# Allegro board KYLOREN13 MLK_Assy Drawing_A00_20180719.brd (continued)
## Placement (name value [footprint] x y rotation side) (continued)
C7205  SC22U6D3V3MX-1-DL-GP  [C603H40]  20.83 75.84 90 bottom
C7206  SCD1U16V2KX-3DLGP  [C402H22]  22.48 79.27 90 top
C7208  SC10U6D3V2MX-2-GP  [C402-TO0D2H28]  11.56 83.33 90 bottom
C7210  SC1U10V2KX-1DLGP  [C402H22]  16.13 83.33 90 top
C7211  SC10U6D3V3MX-DL-GP  [C603H36]  18.67 58.18 0 bottom
C7212  SCD22U10V2KX-2-GP  [C402H22]  18.67 84.47 0 top
C7217  SC220P50V2KX-3DLGP  [C402H22]  20.7 87.78 270 top
C7218  SC220P50V2KX-3DLGP  [C402H22]  22.73 87.78 90 top
C7244  SCD1U16V2KX-3DLGP  [C402H22]  19.68 57.8 0 bottom
C7301  SC1U25V3KX-1-DLGP  [C603H36]  19.68 73.04 180 bottom
C7302  SCD1U25V2KX-1-DL-GP  [C402H22]  21.84 72.92 180 top
C7303  SCD1U25V2KX-1-DL-GP  [C402H22]  22.61 72.92 180 top
C7304  SCD1U25V2KX-1-DL-GP  [C402H22]  23.37 72.92 180 top
C7305  SC10U25V5KX-DL-GP  [C805H58]  25.78 73.55 0 bottom
C7306  SC1U25V2KX-2-GP  [C402H22]  24.13 72.92 180 top
C7307  SCD1U25V2KX-1-DL-GP  [C402H22]  24.89 72.92 180 top
C7401  SC1500P50V2KX-2-DL-GP  [C402H22]  25.27 67.96 180 top
C9106  SC10U6D3V3MX-DL-GP  [C603H36]  157.73 56.15 180 bottom
C9108  SCD1U16V2KX-3DLGP  [C402H22]  158.88 56.53 180 bottom
C9109  SC10U6D3V3MX-DL-GP  [C603H36]  160.66 62.63 270 bottom
C9112  SCD1U16V2KX-3DLGP  [C402H22]  163.56 54.12 180 bottom
C9113  SCD1U16V2KX-3DLGP  [C402H22]  164.34 54.12 180 bottom
C9201  SC1U10V2KX-1DLGP  [C402H22]  172.72 52.22 270 top
CPU1  WHISKEY-LAKE-GP  [BGA1528M2446-1H52]  113.55 78.9 270 bottom
D1701  RB520S30-GP  [SOD523AKH26]  122.17 52.09 90 bottom
D2401  BAT54C-12-GP  [SOT-23-9H44]  109.73 17.8 0 bottom
D2402  RB751V-40H-GP  [SOD323AKH38]  21.74 29.84 90 bottom
D2403  RB520S30-GP  [SOD523AKH26]  87.63 25.42 270 bottom
D2501  BAT54C-12-GP  [SOT-23-9H44]  154.23 77.36 180 bottom
D2502  RB751V-40H-GP  [SOD323AKH38]  158.88 51.33 180 bottom
D2503  BAT54A-11-GP  [SOT-23-9H44]  159.27 73.13 180 bottom
D2601  RB551V30-GP  [SOD323AKH38]  172.85 78.89 0 bottom
D2702  BAT54C-12-GP  [SOT-23-9H44]  6.48 6.62 180 bottom
D4001  RB520S30-GP  [SOD523AKH26]  104.14 19.55 180 bottom
D4002  RB520S30-GP  [SOD523AKH26]  159.26 76.47 180 bottom
D4003  RB520S30-GP  [SOD523AKH26]  161.14 80.87 180 bottom
D4301  P6AF24A-R1-00001-GP  [D4724AKH44]  28.96 74.69 0 bottom
D4302  LBAV99LT1G-1-GP  [SOT23-2D4-312H44]  50.42 13.58 180 bottom
D4303  L30ESD24VC3-2-GP  [SOT23-2D4-312H60]  51.99 16.99 180 bottom
D4304  SMF18A-GP  [SOD123AK-2H43]  145.97 13.23 0 bottom
D4305  RB751V-40H-GP  [SOD323AKH38]  24.26 27.22 90 bottom
D5501  BAT54C-12-GP  [SOT-23-9H44]  124.33 102.63 270 bottom
D5502  BAT54C-12-GP  [SOT-23-9H44]  129.67 98.06 270 bottom
D5701  BAW56-9-GP-U  [SOT23-2D4-312H44]  21.34 61.61 90 bottom
D5702  RB751V-40H-GP  [SOD323AKH38]  27.81 52.22 270 bottom
D6101  RB751V-40H-GP  [SOD323AKH38]  181.61 36.85 180 top
D6102  RB751V-40H-GP  [SOD323AKH38]  184.15 36.85 180 top
D6401  BAT54A-11-GP  [SOT-23-9H44]  130.81 12.97 270 bottom
D7301  NSR20F30NXT5G-GP  [D1608AK-1H13]  26.04 73.3 0 top
D9201  RB751V-40H-GP  [SOD323AKH38]  181.61 48.91 180 top
DB1  DM-ACES-CON14-5-GP-01  [DM-87212-1400N-01]  93.73 15 180 top
DB3  ACES-CON6-58-GP  [50696-00601-001]  96.52 1.16 180 bottom
DCIN1  ACES-CON8-13-GP-U2  [50224-0080N-W02-U]  26.15 83.05 0 bottom
EC1706  SC1KP50V2KX-1DLGP  [C402H22]  152.78 88.28 270 top
EC1707  SCD1U16V2KX-3DLGP  [C402H22]  133.01 50.04 90 bottom
EC1712  SCD1U16V2KX-3DLGP  [C402H22]  129.08 50.85 270 bottom
EC1801  SC10P50V2JN-4DLGP  [C402H22]  127.13 58.82 90 top
EC1803  SC4D7P50V2BN-2-GP  [C402H22]  125.86 59.71 270 bottom
EC1804  SCD1U16V2KX-3DLGP  [C402H22]  156.08 50.06 90 bottom
EC1901  SC10P50V2JN-4DLGP  [C402H22]  27.94 24.53 0 top
EC1903  SC33P50V2JN-3DLGP  [C402H22]  24.89 23.64 270 top
EC2201  SCD1U25V2KX-1-DL-GP  [C402H22]  124.05 83.39 270 top
EC2402  SCD1U25V2KX-1-DL-GP  [C402H22]  100.97 13.2 90 top
EC2403  SCD1U25V2KX-1-DL-GP  [C402H22]  81.56 9.42 180 bottom
EC2501  SC4D7P50V2BN-2-GP  [C402H22]  133.15 61.21 90 bottom
EC2502  SC4D7P50V2BN-2-GP  [C402H22]  150.11 57.8 180 bottom
EC2503  SC10P50V2JN-4DLGP  [C402H22]  136.8 58.73 90 bottom
EC2601  SC10P50V2JN-4DLGP  [C402H22]  163.83 78.89 180 bottom
EC2602  SC10P50V2JN-4DLGP  [C402H22]  163.83 80.41 0 bottom
EC2701  SC10P50V2JN-4DLGP  [C402H22]  30.1 24.15 270 top
EC2709  SCD01U50V2KX-1DLGP  [C402H22]  17.65 14.75 180 bottom
EC2710  SCD01U50V2KX-1DLGP  [C402H22]  5.08 9.54 0 top
EC2711  SCD01U50V2KX-1DLGP  [C402H22]  5.84 9.54 0 top
EC2712  SCD1U25V2KX-1-DL-GP  [C402H22]  19.43 26.43 90 top
EC2713  SCD1U25V2KX-1-DL-GP  [C402H22]  18.16 12.59 90 bottom
EC2714  SCD1U25V2KX-1-DL-GP  [C402H22]  19.43 27.2 90 top
EC2901  SC1KP50V2KX-1DLGP  [C402H22]  19.56 4.08 90 top
EC2902  SC1KP50V2KX-1DLGP  [C402H22]  21.34 4.08 90 top
EC2903  SC1KP50V2KX-1DLGP  [C402H22]  21.31 8.93 270 top
EC2904  SC1KP50V2KX-1DLGP  [C402H22]  24 7.51 0 top
EC2905  SC680P50V2KX-2DLGP  [C402H22]  5.71 12.57 180 bottom
EC2906  SC680P50V2KX-2DLGP  [C402H22]  16.76 26.82 90 bottom
EC2907  SC680P50V2KX-2DLGP  [C402H22]  16.64 22.24 0 bottom
EC2908  SC680P50V2KX-2DLGP  [C402H22]  17.02 23.51 90 bottom
EC3501  SCD1U25V2KX-1-DL-GP  [C402H22]  19.18 43.71 90 top
EC4301  SC10U25V3MX-GP  [C603H40]  25.78 76.73 90 bottom
EC4302  SCD1U25V2KX-1-DL-GP  [C402H22]  26.54 75.58 270 top
EC4306  SC10P50V2JN-4DLGP  [C402H22]  30.1 39.13 90 top
EC4307  SC1KP50V2KX-1DLGP  [C402H22]  148.74 14.06 180 bottom
EC4308  SCD1U50V3KX-DL-GP  [C603H35]  147.75 14.29 180 bottom
EC4309  SC10P50V2JN-4DLGP  [C402H22]  164.21 22.8 0 bottom
EC4310  SC10P50V2JN-4DLGP  [C402H22]  163.86 23.94 270 bottom
EC4311  SCD1U25V2KX-1-DL-GP  [C402H22]  27.81 81.04 270 top
EC4312  SC1KP50V2KX-1DLGP  [C402H22]  26.54 76.35 270 top
EC4313  SCD1U25V2KX-1-DL-GP  [C402H22]  26.54 77.11 270 top
EC4534  SC2D2U25V5KX-2-GP  [C805H54]  55.88 21.86 270 bottom
EC4701  SCD1U25V2KX-1-DL-GP  [C402H22]  92.88 72.42 90 top
EC5001  SCD1U25V2KX-1-DL-GP  [C402H22]  119.75 76.48 270 top
EC5501  SC8P50V2DN-1DL-GP  [C402H22]  100.97 101.87 0 top
EC5503  SC33P50V2JN-3DLGP  [C402H22]  114.05 100.17 180 top
EC5504  SC33P50V2JN-3DLGP  [C402H22]  114.43 98.95 90 top
EC5505  SCD1U50V3KX-DL-GP  [C603H35]  50.04 88.66 270 bottom
EC5506  SC33P50V2JN-3DLGP  [C402H22]  59.69 91.97 90 top
EC6501  SC33P50V2JN-3DLGP  [C402H22]  144.65 10.43 270 top
EC6502  SC33P50V2JN-3DLGP  [C402H22]  144.65 9.67 270 top
EC6503  SC33P50V2JN-3DLGP  [C402H22]  132.72 10.79 270 top
EC6504  SC33P50V2JN-3DLGP  [C402H22]  132.72 10.03 270 top
EC8901  SCD1U25V2KX-1-DL-GP  [C402H22]  132.33 106.95 0 bottom
EC8902  SCD1U25V2KX-1-DL-GP  [C402H22]  97.41 99.33 180 top
EC8903  SCD1U25V2KX-1-DL-GP  [C402H22]  93.73 98.93 270 top
EC8904  SCD1U25V2KX-1-DL-GP  [C402H22]  68.71 80.54 270 top
EC8905  SC1U10V2KX-1DLGP  [C402H22]  96.31 86.13 180 top
EC8906  SCD1U25V2KX-1-DL-GP  [C402H22]  99.87 82.58 0 top
EC8907  SCD1U25V2KX-1-DL-GP  [C402H22]  122.1 99.36 180 top
EC8908  SCD1U25V2KX-1-DL-GP  [C402H22]  147.8 20.29 180 top
EC8909  SCD1U25V2KX-1-DL-GP  [C402H22]  157.28 29.96 270 top
EC8910  SCD1U25V2KX-1-DL-GP  [C402H22]  158.12 21.56 270 top
EC8911  SCD1U25V2KX-1-DL-GP  [C402H22]  170.74 53.74 90 top
EC8912  SCD1U25V2KX-1-DL-GP  [C402H22]  47.75 87.67 0 bottom
EC8913  SCD1U25V2KX-1-DL-GP  [C402H22]  52.58 59.89 270 bottom
EC8914  SCD1U25V2KX-1-DL-GP  [C402H22]  125.91 27.3 90 bottom
EC8915  SCD1U25V2KX-1-DL-GP  [C402H22]  158.83 30.96 270 bottom
EC8916  SCD1U25V2KX-1-DL-GP  [C402H22]  170.74 52.9 90 top
EC8917  SCD1U25V2KX-1-DL-GP  [C402H22]  113.21 23.28 0 top
EC8918  SCD1U25V2KX-1-DL-GP  [C402H22]  80.54 19.5 0 top
EC8919  SCD1U25V2KX-1-DL-GP  [C402H22]  113.67 6.44 0 top
EC8920  SCD1U25V2KX-1-DL-GP  [C402H22]  136.58 5.25 180 top
EC8921  SCD1U25V2KX-1-DL-GP  [C402H22]  112.42 22.45 180 top
EC8922  SCD1U25V2KX-1-DL-GP  [C402H22]  166.37 20.08 90 top
EC8923  SCD1U25V2KX-1-DL-GP  [C402H22]  171.58 34.44 90 top
EC8924  SCD1U25V2KX-1-DL-GP  [C402H22]  186.56 46.25 180 top
EC8925  SCD1U25V2KX-1-DL-GP  [C402H22]  131.95 98.8 180 bottom
EC8926  SCD1U25V2KX-1-DL-GP  [C402H22]  154.38 101.14 0 bottom
EC8927  SCD1U25V2KX-1-DL-GP  [C402H22]  166.88 11.24 90 top
EC8928  SCD1U25V2KX-1-DL-GP  [C402H22]  101.35 24.66 270 bottom
EC8929  SCD1U25V2KX-1-DL-GP  [C402H22]  168.91 45.99 270 bottom
EC8930  SCD1U25V2KX-1-DL-GP  [C402H22]  86.36 51.45 180 top
EC8931  SCD1U25V2KX-1-DL-GP  [C402H22]  132.99 33.77 0 top
EC8932  SCD1U25V2KX-1-DL-GP  [C402H22]  142.65 46.09 90 top
EC8933  SCD1U25V2KX-1-DL-GP  [C402H22]  120.34 58.65 90 top
EC8934  SCD1U25V2KX-1-DL-GP  [C402H22]  120.31 60.66 90 top
EC8937  SCD1U25V2KX-1-DL-GP  [C402H22]  71.5 86.38 180 top
EC8938  SCD1U25V2KX-1-DL-GP  [C402H22]  71.5 73.81 0 top
EC8939  SCD1U25V2KX-1-DL-GP  [C402H22]  118.36 32.81 180 top
EC8940  SCD1U25V2KX-1-DL-GP  [C402H22]  55.88 48.66 180 top
EC8941  SCD1U25V2KX-1-DL-GP  [C402H22]  49.15 43.83 270 top
EC8942  SCD1U25V2KX-1-DL-GP  [C402H22]  69.9 32.63 270 top
EC8943  SCD1U25V2KX-1-DL-GP  [C402H22]  50.31 66.31 270 top
EC8944  SCD1U25V2KX-1-DL-GP  [C402H22]  57.36 55.26 90 top
EC8945  SCD1U25V2KX-1-DL-GP  [C402H22]  44.31 49.98 270 top
EC8946  SCD1U25V2KX-1-DL-GP  [C402H22]  42.08 23.06 270 top
EC8947  SCD1U25V2KX-1-DL-GP  [C402H22]  55.32 20 0 top
EC8948  SCD1U25V2KX-1-DL-GP  [C402H22]  73.41 29.72 180 top
EC8949  SCD1U25V2KX-1-DL-GP  [C402H22]  121.16 30.12 90 top
EC8950  SCD1U25V2KX-1-DL-GP  [C402H22]  85.67 24.65 0 top
ED301  AZ5125-02S-R7G-GP  [SOT23-2D4-312H46]  117.73 98.06 180 bottom
ED1701  AZ5125-02S-R7G-GP  [SOT23-2D4-312H46]  137.41 53.49 180 bottom
ED1702  AZ5125-02S-R7G-GP  [SOT23-2D4-312H46]  163.45 83.2 180 bottom
ED1703  AZ5125-02S-R7G-GP  [SOT23-2D4-312H46]  167 83.2 180 bottom
ED1704  AZ5125-02S-R7G-GP  [SOT23-2D4-312H46]  157.73 83.2 180 bottom
ED1801  AZ5125-02S-R7G-GP  [SOT23-2D4-312H46]  135.48 49.86 0 bottom
ED2403  AZ5125-02S-R7G-GP  [SOT23-2D4-312H46]  108.46 15 180 bottom
ED2901  AZ5125-02S-R7G-GP  [SOT23-2D4-312H46]  4.83 15.89 270 bottom
ED2902  AZ5125-02S-R7G-GP  [SOT23-2D4-312H46]  19.56 26.18 90 bottom
ED2903  AZ5125-02S-R7G-GP  [SOT23-2D4-312H46]  16.51 29.74 180 bottom
ED3501  L05ESDL5V0NA-4-GP  [SLP2510P8-1H22]  18.67 40.15 90 top
ED3503  AZC099-04S-2-GP  [SOT-6H58]  19.56 35.96 0 bottom
ED4304  LBAV99LT1G-1-GP  [SOT23-2D4-312H44]  161.34 20.29 0 bottom
ED4305  LBAV99LT1G-1-GP  [SOT23-2D4-312H44]  162.86 25.93 180 bottom
ED4306  LBAV99LT1G-1-GP  [SOT23-2D4-312H44]  161.34 22.78 0 bottom
ED5501  AZC099-04S-2-GP  [SOT-6H58]  121.28 99.21 270 bottom
ED5502  AZ5125-02S-R7G-GP  [SOT23-2D4-312H46]  47.37 90.32 180 bottom
ED5701  AZ1043-04F-R7G-GP  [DFN10G2510H22]  17.14 61.11 90 top
ED5702  AZ1043-04F-R7G-GP  [DFN10G2510H22]  17.14 65.04 270 top
ED5703  AZ1043-04F-R7G-GP  [DFN10G2510H22]  15.62 62.63 90 bottom
ED6301  L05ESDL5V0NA-4-GP  [SLP2510P8-1H22]  169.67 15.26 90 top
ED6401  AZ5125-02S-R7G-GP  [SOT23-2D4-312H46]  111.76 15.13 270 bottom
ED7301  L05ESDL5V0NA-4-GP  [SLP2510P8-1H22]  16 77.79 270 top
ED7302  L05ESDL5V0NA-4-GP  [SLP2510P8-1H22]  15.11 89.55 270 top
ED7303  L05ESDL5V0NA-4-GP  [SLP2510P8-1H22]  14.73 86.25 90 top
ED7304  AZ5315-02F-GP  [SOT883-1D0-321H20]  21.72 90.06 0 top
ED7305  AZ5315-02F-GP  [SOT883-1D0-321H20]  32.51 85.62 0 bottom
ED9202  AZC099-04S-2-GP  [SOT-6H58]  173.02 48.99 270 bottom
EL3505  COIL-90OHM-100MHZ-5-GP  [L125100-4P-4H24]  18.92 38.88 270 bottom
EL4301  0R0805-PAD-2-GP-U  [0R0805-PAD-1-U]  30.71 77.11 90 top
EL4302  0R0805-PAD-2-GP-U  [0R0805-PAD-1-U]  30.71 75.2 90 top
EL4303  0R0805-PAD-2-GP-U  [0R0805-PAD-1-U]  26.04 79.14 180 top
EL4304  0R0805-PAD-2-GP-U  [0R0805-PAD-1-U]  24.13 79.14 180 top
EL5501  COIL-90OHM-100MHZ-5-GP  [L125100-4P-4H24]  124.21 99.84 0 bottom
EL6601  COIL-90OHM-100MHZ-5-GP  [L125100-4P-4H24]  174.04 43.33 90 top
EL6603  COIL-90OHM-100MHZ-5-GP  [L125100-4P-4H24]  175.64 43.33 90 top
EL7201  COIL-90OHM-100MHZ-5-GP  [L125100-4P-4H24]  16.64 85.36 180 top
EL7202  COIL-90OHM-100MHZ-5-GP  [L125100-4P-4H24]  16.64 87.14 180 top
EL7301  0R5J-5-GP  [R805H24]  23.88 73.55 180 bottom
EL7302  0R5J-5-GP  [R805H24]  21.97 73.55 180 bottom
ER2901  0R0402-PAD-2-GP  [0R0402-PAD-1]  23.11 7.51 0 top
ER2902  0R0402-PAD-2-GP  [0R0402-PAD-1]  21.92 7.46 0 top
ER2903  0R0402-PAD-2-GP  [0R0402-PAD-1]  21.23 4.84 90 top
ER2904  0R0402-PAD-2-GP  [0R0402-PAD-1]  19.56 4.84 90 top
F5502  POLYSW-1D1A6V-9-GP-U  [POLYSW-2114H30]  106.63 103.14 0 top
F5503  POLYSW-1D1A24V-GP-U  [POLYSW-4633-UH43]  54.48 91.61 0 bottom
F5504  POLYSW-1D1A6V-9-GP-U  [POLYSW-2114H30]  57.4 92.6 90 top
F5701  POLYSW-1D1A6V-9-GP-U  [POLYSW-2114H30]  15.75 65.68 180 bottom
F6501  POLYSW-1D1A6V-9-GP-U  [POLYSW-2114H30]  71.5 15.89 270 bottom
FAN1  ACES-CON4-29-GP  [50224-0040N-001]  168.55 75.3 180 bottom
FC1102  SC2D2U6D3V2MX-DL-GP  [C402H22]  119.45 55.75 90 top
FC1103  SC2D2U6D3V2MX-DL-GP  [C402H22]  110.74 59.33 270 top
FC1801  SC4D7P50V2BN-2-GP  [C402H22]  125.86 58.95 270 bottom
FC2701  SC10P50V2JN-4DLGP  [C402H22]  30.61 19.32 180 top
FC5501  SC10P50V2JN-4DLGP  [C402H22]  103 103.27 90 top
FC5502  SC10P50V2JN-4DLGP  [C402H22]  104.52 101.75 270 top
FC6101  SC10P50V2JN-4DLGP  [C402H22]  178 35.83 270 top
FC8906  SC4D7P50V2BN-2-GP  [C402H22]  167.26 51.58 180 bottom
FC8907  SC4D7P50V2BN-2-GP  [C402H22]  168.28 55.9 270 bottom
FC8914  SC4D7P50V2BN-2-GP  [C402H22]  46.1 51.07 270 top
FC8916  SC4D7P50V2BN-2-GP  [C402H22]  170.74 52.09 90 top
FC8917  SC4D7P50V2BN-2-GP  [C402H22]  46.1 51.83 270 top
FC8919  SC4D7P50V2BN-2-GP  [C402H22]  56.13 23.26 270 bottom
FC8920  SC4D7P50V2BN-2-GP  [C402H22]  42.93 29.99 180 top
FC8925  SC4D7P50V2BN-2-GP  [C402H22]  172.29 41.17 90 top
FC8930  SC4D7P50V2BN-2-GP  [C402H22]  172.29 42 90 top
FC8933  SC4D7P50V2BN-2-GP  [C402H22]  157.85 69.91 0 bottom
FC8938  SC4D7P50V2BN-2-GP  [C402H22]  78.99 15 270 top
FC8940  SC4D7P50V2BN-2-GP  [C402H22]  171.58 33.67 90 top
FC8941  SC4D7P50V2BN-2-GP  [C402H22]  78.99 15.77 270 top
FC8942  SC4D7P50V2BN-2-GP  [C402H22]  171.58 35.2 90 top
FC8943  SC4D7P50V2BN-2-GP  [C402H22]  145.29 72.15 270 bottom
FC8945  SC4D7P50V2BN-2-GP  [C402H22]  147.7 93.24 90 bottom
FC8946  SC4D7P50V2BN-2-GP  [C402H22]  64.05 49.94 0 bottom
FC8947  SC4D7P50V2BN-2-GP  [C402H22]  65.45 49.94 0 bottom
FC8948  SC4D7P50V2BN-2-GP  [C402H22]  110.91 50.57 0 bottom
FC8949  SC4D7P50V2BN-2-GP  [C402H22]  139.74 48.54 0 bottom
FC8950  SC4D7P50V2BN-2-GP  [C402H22]  99.61 34.32 180 bottom
FC8951  SC4D7P50V2BN-2-GP  [C402H22]  52.45 30.24 180 bottom
FC8952  SC4D7P50V2BN-2-GP  [C402H22]  82.72 30.63 180 bottom
FC8953  SC4D7P50V2BN-2-GP  [C402H22]  101.22 30.37 180 bottom
FC8954  SC4D7P50V2BN-2-GP  [C402H22]  132.21 29.61 180 bottom
FPR1  PTWO-CON8-11-GP  [FH52-8S-D5SH]  178.65 49.2 270 bottom
FSW1  SW-SLIDE3P-11-GP  [MSS3-Q-T-R]  33.02 10.56 0 bottom
G1801  GAP-OPEN  [CON2O-U]  153.67 49.17 90 bottom
G5701  GAP-CLOSE-PWR-3-GP  [GAP-CLOSE-PWR-3]  22.89 32.02 180 bottom
H1  HOLE335R178-GP  [HOLE335R178]  29.05 94.3 180 bottom
H2  HOLE335R178-GP  [HOLE335R178]  10.95 13.15 180 bottom
H3  HOLE335R178-GP  [HOLE335R178]  104.05 4.3 180 bottom
H5  HOLE335R178-GP  [HOLE335R178]  166.55 89.9 180 bottom
H6  HOLE276R150-GP  [HOLE276R150]  142.35 92 180 bottom
H7  HOLE276R150-GP  [HOLE276R150]  81.35 92 180 bottom
H8  HOLE276R150-GP  [HOLE276R150]  142.35 67.7 180 bottom
H9  HOLE276R150-GP  [HOLE276R150]  81.35 67.7 180 bottom
H10  HOLE335R178-GP  [HOLE335R178]  152.05 34.95 180 bottom
HALL1  HGDEDM013A-GP  [OPLGA4-0913H22]  4.3 73 180 top
HDMI1  SKT-HDMI23-167-GP-U  [SKT-HDMI23-188137-4]  4.6 61.5 90 bottom
HPMIC1  AUDIO-JK569-GP  [2SJ3095-099111F]  3.85 24.1 90 bottom
HS1  STF237R113H62-10-GP  [STF237R113H62]  12.05 73.8 180 bottom
IOBD1  STAR-CON50-2-GP-U  [300E50-1030RA-G4]  173.05 40.8 180 bottom
KBBD1  PTWO-CON30-18-GP  [196528-30041-3]  52.05 8.3 180 bottom
KBBL1  ACES-CON4-90-GP-U  [50698-00401-W01-U]  74.05 6.3 180 bottom
L5701  0R0603-PAD-2-GP-U  [0R0603-PAD-1-U]  26.77 54.35 0 bottom
L5702  0R0603-PAD-2-GP-U  [0R0603-PAD-1-U]  26.8 46.88 90 bottom
L5703  0R0603-PAD-2-GP-U  [0R0603-PAD-1-U]  26.8 45.48 90 bottom
L5704  0R0603-PAD-2-GP-U  [0R0603-PAD-1-U]  26.8 48.15 90 bottom
L5705  0R0603-PAD-2-GP-U  [0R0603-PAD-1-U]  26.8 44.21 90 bottom
L7101  0R0402-PAD-2-GP  [0R0402-PAD-1]  33.4 87.52 90 top
LCD1  STAR-CON50-2-GP-U  [300E50-1030RA-G4]  99.25 102.3 0 bottom
LED1  PTWO-CON4-21-GP  [196335-04021-3]  114.55 6.3 180 bottom
NOREF  -  []  91.24 68.69 90 top
NOREF#2  -  []  2.93 74.52 0 top
NOREF#3  -  []  0 -17 0 top
NOREF#4  -  [unnamed#2]  -4.38 11.53 0 top
NOREF#5  -  [unnamed#2]  176.83 102.77 0 top
NOREF#6  -  []  7.62 1.54 0 top
NOREF#7  *  [unnamed#2]  183.11 -103.1 0 top
NOREF#8  -  [unnamed#2]  -5.04 49.85 0 top
NOREF#9  -  []  138.6 92.95 90 top
NOREF#10  -  []  160.69 93.99 90 top
NOREF#11  -  [unnamed#2]  0.41 98.53 0 top
NOREF#12  -  []  138.6 143.04 0 top
NOREF#13  -  []  105.35 67.59 90 top
NOREF#14  -  []  -1.59 85.52 0 top
NOREF#15  -  [unnamed#2]  191.69 -99.25 0 top
NOREF#16  -  []  -1.59 85.52 0 top
NOREF#17  *  [unnamed#2]  154.56 92.47 0 top
NOREF#18  -  []  12.13 74.44 90 top
NOREF#19  -  [unnamed#2]  196.16 -13.78 0 top
NOREF#20  -  []  -2.03 -54.85 270 top
NOREF#21  *  [unnamed#2]  32.38 23.51 0 top
NOREF#22  -  []  90.55 66.9 0 top
NOREF#23  -  []  12.13 74.44 90 top
NOREF#24  -  []  160.69 93.49 90 top
NOREF#25  -  []  139.14 137.04 0 top
NOREF#26  -  []  0 -17 0 top
NOREF#27  *  [unnamed#2]  160.78 4.21 0 top
NOREF#28  -  []  94.5 65.9 0 top
NOREF#29  -  []  201.4 92.45 0 top
NOREF#30  -  [unnamed#2]  197.54 -51.26 0 top
NOREF#31  -  []  91.24 68.04 0 top
NOREF#32  *  [unnamed#2]  183.91 103.69 0 top
NOREF#33  -  []  144.59 142.49 0 top
NOREF#34  -  []  -1.59 85.52 0 top
NOREF#35  -  [unnamed#2]  63.02 105.18 0 top
NOREF#36  *  [unnamed#2]  24 89.68 0 top
NOREF#37  *  [unnamed#2]  4.14 104.66 0 top
NOREF#38  -  [unnamed#2]  3.7 3.3 0 top
NOREF#39  -  []  0 -17 0 top
NOREF#40  -  [unnamed#2]  156.85 107.4 0 top
NOREF#41  -  []  2.93 74.52 0 top
NOREF#42  -  []  127.15 6.19 0 top
NOREF#43  -  []  96.27 51.45 0 top
NOREF#44  -  []  17.96 109.21 180 top
NOREF#45  -  []  139.14 98.94 90 top
NOREF#46  *  [unnamed#2]  18.75 9.95 0 top
NOREF#47  -  [unnamed#2]  189.87 31.26 0 top
NOREF#48  -  []  68.45 17.16 0 top
NOREF#49  -  [unnamed#2]  128.75 -106.86 0 top
NOREF#50  -  []  12.13 74.44 90 top
NOREF#51  -  [unnamed#2]  16.4 -103.41 0 top
NOREF#52  -  []  173.81 -111.28 0 top
NOREF#53  -  []  0 -17 0 top
NOREF#54  -  [unnamed#2]  -5.37 58.98 0 top
NOREF#55  -  []  2.93 74.52 0 top
NOREF#56  -  [unnamed#2]  197.83 -61.34 0 top
NOREF#57  -  []  65.45 -8.19 180 top
NOREF#58  *  [unnamed#2]  183.11 -103.1 180 bottom
NOREF#59  *  [unnamed#2]  161.09 31.23 180 bottom
NOREF#60  -  []  7.62 1.54 180 bottom
NOREF#61  *  [unnamed#2]  183.91 103.69 180 bottom
NOREF#62  -  []  7.75 97.68 180 bottom
NOREF#63  -  []  -2.03 -69.58 90 bottom
NOREF#64  -  []  100.58 50.18 180 bottom
NOREF#65  *  [unnamed#2]  4.14 104.66 180 bottom
NOREF#66  -  []  149.86 88.41 180 bottom
NOREF#67  *  [unnamed#2]  154.56 92.47 180 bottom
NOREF#68  -  []  180.21 33.17 180 bottom
NOREF#69  -  []  84.2 75.46 180 bottom
NOREF#70  *  [unnamed#2]  89.79 57.93 180 bottom
NOREF#71  -  []  196.98 -94.72 180 bottom
NOREF#72  *  [unnamed#2]  12.32 6.75 180 bottom
NOREF#73  *  [unnamed#2]  36.7 96.54 180 bottom
PC1001  SC22U6D3V3MX-1-DL-GP  [C603H40]  72.39 69.23 0 bottom
PC1002  SC22U6D3V3MX-1-DL-GP  [C603H40]  68.58 79.27 270 top
PC1003  SC22U6D3V3MX-1-DL-GP  [C603H40]  89.58 87.66 0 top
PC1004  SC22U6D3V3MX-1-DL-GP  [C603H40]  110.48 81.86 90 top
PC1005  SC22U6D3V3MX-1-DL-GP  [C603H40]  105.45 77.37 270 top
PC1006  SC22U6D3V3MX-1-DL-GP  [C603H40]  68.45 86.63 0 bottom
PC1007  SC22U6D3V3MX-1-DL-GP  [C603H40]  113.94 81.81 270 top
PC1008  SC22U6D3V3MX-1-DL-GP  [C603H40]  113.94 78 270 top
PC1009  SC22U6D3V3MX-1-DL-GP  [C603H40]  69.72 86.63 0 bottom
PC1010  SC22U6D3V3MX-1-DL-GP  [C603H40]  117.26 79.86 90 top
PC1011  SC22U6D3V3MX-1-DL-GP  [C603H40]  115.28 74.22 0 top
PC1012  SC22U6D3V3MX-1-DL-GP  [C603H40]  116.55 74.22 0 top
PC1013  SC22U6D3V3MX-1-DL-GP  [C603H40]  117.82 74.22 0 top
PC1014  SC22U6D3V3MX-1-DL-GP  [C603H40]  114.01 74.22 0 top
PC1015  SC22U6D3V3MX-1-DL-GP  [C603H40]  113.94 83.08 270 top
PC1016  SC22U6D3V3MX-1-DL-GP  [C603H40]  105.45 76.1 270 top
PC1017  SC22U6D3V3MX-1-DL-GP  [C603H40]  112.18 74.19 0 top
PC1018  SC22U6D3V3MX-1-DL-GP  [C603H40]  68.58 77.62 270 top
PC1019  SC22U6D3V3MX-1-DL-GP  [C603H40]  70.23 73.42 0 top
PC1020  SC22U6D3V3MX-1-DL-GP  [C603H40]  117.26 82.4 90 top
PC1021  SC22U6D3V3MX-1-DL-GP  [C603H40]  110.48 83.13 90 top
PC1022  SC22U6D3V3MX-1-DL-GP  [C603H40]  68.58 75.96 270 top
PC1023  SC22U6D3V3MX-1-DL-GP  [C603H40]  68.58 85.24 270 top
PC1024  SC22U6D3V3MX-1-DL-GP  [C603H40]  113.94 79.27 270 top
PC1025  SC22U6D3V3MX-1-DL-GP  [C603H40]  113.94 80.54 270 top
PC1026  SC22U6D3V3MX-1-DL-GP  [C603H40]  68.58 81.93 270 top
PC1027  SC22U6D3V3MX-1-DL-GP  [C603H40]  91.36 87.78 0 top
PC1028  SC22U6D3V3MX-1-DL-GP  [C603H40]  110.48 80.59 90 top
PC1029  SC22U6D3V3MX-1-DL-GP  [C603H40]  88.27 87.65 0 top
PC1030  SC22U6D3V3MX-1-DL-GP  [C603H40]  116.84 88.16 0 top
PC1031  SC22U6D3V3MX-1-DL-GP  [C603H40]  110.49 76.85 90 top
PC1032  SC22U6D3V3MX-1-DL-GP  [C603H40]  110.48 79.32 90 top
PC1034  SC22U6D3V3MX-1-DL-GP  [C603H40]  68.58 83.58 270 top
PC1036  SC22U6D3V3MX-1-DL-GP  [C603H40]  68.58 77.62 90 bottom
PC1037  SC22U6D3V3MX-1-DL-GP  [C603H40]  73.02 56.74 270 bottom
PC1038  SC22U6D3V3MX-1-DL-GP  [C603H40]  101.52 84.99 90 top
PC1039  SC22U6D3V3MX-1-DL-GP  [C603H40]  77.98 63.14 270 bottom
PC1040  SC22U6D3V3MX-1-DL-GP  [C603H40]  92.37 71.4 90 top
PC1041  SC22U6D3V3MX-1-DL-GP  [C603H40]  97.71 83.08 90 top
PC1042  SC22U6D3V3MX-1-DL-GP  [C603H40]  101.27 75.46 270 top
PC1043  SC22U6D3V3MX-1-DL-GP  [C603H40]  88.31 85.12 180 top
PC1044  SC22U6D3V3MX-1-DL-GP  [C603H40]  101.27 76.73 270 top
PC1045  SC22U6D3V3MX-1-DL-GP  [C603H40]  67.82 66.69 90 bottom
PC1046  SC22U6D3V3MX-1-DL-GP  [C603H40]  101.26 78 270 top
PC1047  SC22U6D3V3MX-1-DL-GP  [C603H40]  85.03 78.66 0 top
PC1048  SC22U6D3V3MX-1-DL-GP  [C603H40]  97.71 81.81 90 top
PC1049  SC22U6D3V3MX-1-DL-GP  [C603H40]  92.63 86.13 180 top
PC1050  SC22U6D3V3MX-1-DL-GP  [C603H40]  97.71 75.46 90 top
PC1051  SC22U6D3V3MX-1-DL-GP  [C603H40]  77.98 60.6 270 bottom
PC1052  SC22U6D3V3MX-1-DL-GP  [C603H40]  90.85 85.12 180 top
PC1053  SC22U6D3V3MX-1-DL-GP  [C603H40]  87.04 85.12 180 top
PC1054  SC22U6D3V3MX-1-DL-GP  [C603H40]  97.41 85.74 180 top
PC1055  SC22U6D3V3MX-1-DL-GP  [C603H40]  85.77 85.12 180 top
PC1056  SC22U6D3V3MX-1-DL-GP  [C603H40]  90.59 75.97 180 top
PC1057  SC22U6D3V3MX-1-DL-GP  [C603H40]  74.3 70.63 90 bottom
PC1058  SC22U6D3V3MX-1-DL-GP  [C603H40]  97.71 76.73 90 top
PC1059  SC22U6D3V3MX-1-DL-GP  [C603H40]  89.58 85.12 180 top
PC1060  SC22U6D3V3MX-1-DL-GP  [C603H40]  93.39 73.43 90 top
PC1061  SC22U6D3V3MX-1-DL-GP  [C603H40]  97.71 78 90 top
PC1062  SC22U6D3V3MX-1-DL-GP  [C603H40]  97.71 79.27 90 top
PC1063  SC22U6D3V3MX-1-DL-GP  [C603H40]  86.3 78.66 0 top
PC1064  SC22U6D3V3MX-1-DL-GP  [C603H40]  67.82 68.09 90 bottom
PC1065  SC22U6D3V3MX-1-DL-GP  [C603H40]  68.07 56.91 90 bottom
PC1066  SC22U6D3V3MX-1-DL-GP  [C603H40]  97.71 80.54 90 top
PC1067  SC22U6D3V3MX-1-DL-GP  [C603H40]  101.26 79.27 270 top
PC1068  SC22U6D3V3MX-1-DL-GP  [C603H40]  77.98 61.87 270 bottom
PC1069  SC22U6D3V3MX-1-DL-GP  [C603H40]  73.02 58.01 270 bottom
PC1070  SC22U6D3V3MX-1-DL-GP  [C603H40]  67.82 65.42 90 bottom
PC1071  SC22U6D3V3MX-1-DL-GP  [C603H40]  120.14 77.5 270 top
PC1072  SC22U6D3V3MX-1-DL-GP  [C603H40]  125.01 85.37 90 top
PC1073  SC22U6D3V3MX-1-DL-GP  [C603H40]  119.04 84.23 270 top
PC1074  SC22U6D3V3MX-1-DL-GP  [C603H40]  130.05 107.08 0 bottom
PC1075  SC22U6D3V3MX-1-DL-GP  [C603H40]  120.14 78.77 270 top
PC1076  SC22U6D3V3MX-1-DL-GP  [C603H40]  121.07 82.7 90 top
PC1077  SC22U6D3V3MX-1-DL-GP  [C603H40]  121.07 81.43 90 top
PC1078  SC22U6D3V3MX-1-DL-GP  [C603H40]  131.32 107.08 0 bottom
PC1079  SC22U6D3V3MX-1-DL-GP  [C603H40]  116.64 84.96 90 top
PC1080  SC22U6D3V3MX-1-DL-GP  [C603H40]  110.48 78.05 90 top
PC1081  SC22U6D3V3MX-1-DL-GP  [C603H40]  113.94 76.73 270 top
PC1082  SC22U6D3V3MX-1-DL-GP  [C603H40]  117.26 78.59 90 top
PC1083  SC22U6D3V3MX-1-DL-GP  [C603H40]  117.26 81.13 90 top
PC1084  SC22U6D3V3MX-1-DL-GP  [C603H40]  117.26 77.32 90 top
PC4401  SC10U25V5KX-DL-GP  [C805H58]  36.96 68.98 0 bottom
PC4402  SC10U25V5KX-DL-GP  [C805H58]  33.66 64.2 90 bottom
PC4403  SC10U25V5KX-DL-GP  [C805H58]  36.2 59.84 180 bottom
PC4404  SC10U25V5KX-DL-GP  [C805H58]  33.66 60.52 90 bottom
PC4405  SC10U25V5KX-DL-GP  [C805H58]  33.66 62.35 90 bottom
PC4406  SCD1U25V2KX-1-DL-GP  [C402H22]  50.8 60.98 270 top
PC4407  SC10U25V5KX-DL-GP  [C805H58]  45.09 52.09 90 bottom
PC4408  SC10U25V5KX-DL-GP  [C805H58]  45.09 50.18 90 bottom
PC4409  SC10U25V5KX-DL-GP  [C805H58]  52.6 27.32 0 bottom
PC4410  SC10U25V5KX-DL-GP  [C805H58]  54.48 51.71 180 bottom
PC4411  SC10U25V5KX-DL-GP  [C805H58]  45.09 48.28 90 bottom
PC4412  SC10U25V5KX-DL-GP  [C805H58]  56.26 27.32 0 bottom
PC4413  SC10U25V5KX-DL-GP  [C805H58]  139.06 14.24 180 bottom
PC4414  SC10U25V5KX-DL-GP  [C805H58]  137.16 14.24 180 bottom
PC4415  SC4D7U6D3V3KX-DLGP  [C603H36]  34.04 52.09 90 bottom
PC4416  SC1U25V3KX-1-DLGP  [C603H36]  32.28 50.64 270 bottom
PC4417  SC1U25V3KX-1-DLGP  [C603H36]  34.7 50.64 90 bottom
PC4418  SC22U25V5MX-GP  [C805H58]  54.41 27.32 0 bottom
PC4419  SC1U25V3KX-1-DLGP  [C603H36]  30.73 49.29 90 bottom
PC4420  SCD022U16V2KX-3DLGP  [C402H22]  29.97 48.28 270 top
PC4421  SC4D7U6D3V3KX-DLGP  [C603H36]  40.77 49.42 270 bottom
PC4422  SC4D7U6D3V3KX-DLGP  [C603H36]  33.27 46.37 180 bottom
PC4423  SCD22U25V3KX-DL-GP  [C603H36]  40.01 46.25 90 bottom
PC4424  SC1U25V3KX-1-DLGP  [C603H36]  37.97 41.29 0 bottom
PC4425  SC1U10V2KX-1DLGP  [C402H22]  37.59 42.94 90 bottom
PC4426  SC1U25V3KX-1-DLGP  [C603H36]  36.8 41.29 0 bottom
PC4427  SC10U25V5KX-DL-GP  [C805H58]  143.89 13.1 180 bottom
PC4428  SC10U25V5KX-DL-GP  [C805H58]  141.99 13.1 180 bottom
PC4429  SC4700P25V2KX-4-GP  [C402H22]  36.45 44.47 0 bottom
PC4430  SC10P50V2JN-4DLGP  [C402H22]  30.1 40.66 270 top
PC4431  SCD01U25V2KX-3DLGP  [C402H22]  32.38 40.02 90 top
PC4432  SC1KP50V2KX-1DLGP  [C402H22]  34.04 40.02 90 top
PC4433  SC1KP50V2KX-1DLGP  [C402H22]  32.89 41.29 0 top
PC4434  SC22U25V5MX-GP  [C805H58]  45.09 46.5 90 bottom
PC4435  SC1KP50V2KX-1DLGP  [C402H22]  38.99 56.15 0 top
PC4436  SCD22U25V3KX-DL-GP  [C603H36]  36.58 51.07 180 bottom
PC4437  SC22U25V5MX-GP  [C805H58]  52.7 51.71 180 bottom
PC4438  SCD1U16V2KX-3DLGP  [C402H22]  30.23 38.88 90 bottom
PC4439  SC1U25V3KX-1-DLGP  [C603H36]  39.37 44.47 180 bottom
PC4440  SC1U25V3KX-1-DLGP  [C603H36]  33.66 44.47 90 bottom
PC4445  SCD1U16V2KX-3DLGP  [C402H22]  31.5 29.61 90 bottom
PC4501  SCD1U25V2KX-1-DL-GP  [C402H22]  125.86 24.02 90 bottom
PC4502  SC10U25V5KX-DL-GP  [C805H58]  131.19 25.29 270 bottom
PC4503  SC10U25V5KX-DL-GP  [C805H58]  125.98 25.29 90 bottom
PC4504  SC10U25V5KX-DL-GP  [C805H58]  130.56 23.39 270 bottom
PC4505  SC10U25V5KX-DL-GP  [C805H58]  61.85 15.26 180 bottom
PC4506  SCD1U25V2KX-1-DL-GP  [C402H22]  121.28 25.55 90 bottom
PC4507  SC4D7U6D3V3KX-DLGP  [C603H36]  123.32 17.42 90 bottom
PC4508  SCD1U25V2KX-1-DL-GP  [C402H22]  130.18 18.69 270 bottom
PC4509  SC22U6D3V3MX-1-DL-GP  [C603H40]  115.19 25.8 0 bottom
PC4510  SC22U6D3V3MX-1-DL-GP  [C603H40]  113.79 19.58 180 bottom
PC4511  SC22U6D3V3MX-1-DL-GP  [C603H40]  115.06 19.58 180 bottom
PC4512  SC22U6D3V3MX-1-DL-GP  [C603H40]  117.86 26.43 0 bottom
PC4513  SCD1U25V2KX-1-DL-GP  [C402H22]  112.78 25.67 0 bottom
PC4514  SC22U6D3V3MX-1-DL-GP  [C603H40]  75.18 19.07 180 bottom
PC4515  SC22U6D3V3MX-1-DL-GP  [C603H40]  77.72 19.07 180 bottom
PC4516  SC22U6D3V3MX-1-DL-GP  [C603H40]  76.45 19.07 180 bottom
PC4517  SC22U6D3V3MX-1-DL-GP  [C603H40]  75.69 25.93 0 bottom
PC4518  SCD1U16V2KX-3DLGP  [C402H22]  73.41 25.8 0 bottom
PC4519  SC10U25V5KX-DL-GP  [C805H58]  60.07 15 180 bottom
PC4520  SC4D7U6D3V3KX-DLGP  [C603H36]  64.26 25.67 0 bottom
PC4521  SCD1U25V2KX-1-DL-GP  [C402H22]  68.58 16.78 270 bottom
PC4522  SCD1U25V2KX-1-DL-GP  [C402H22]  60.45 19.58 0 bottom
PC4523  SC10U25V5KX-DL-GP  [C805H58]  59.05 19.58 0 bottom
PC4524  SC2D2U10V3KX-1DLGP-U  [C603H36]  65.53 25.67 0 bottom
PC4525  SC22U6D3V3MX-1-DL-GP  [C603H40]  116.59 26.43 0 bottom
PC4526  SC1KP50V2KX-1DLGP  [C402H22]  62.1 25.93 0 bottom
PC4527  SC22U6D3V3MX-1-DL-GP  [C603H40]  74.42 25.93 0 bottom
PC4528  SCD1U25V2KX-1-DL-GP  [C402H22]  77.98 25.8 0 bottom
PC4529  SC22U6D3V3MX-1-DL-GP  [C603H40]  76.96 25.93 0 bottom
PC4530  SCD1U25V2KX-1-DL-GP  [C402H22]  59.05 23.13 90 bottom
PC4531  SCD1U25V2KX-1-DL-GP  [C402H22]  60.58 25.93 0 bottom
PC4532  SCD1U25V2KX-1-DL-GP  [C402H22]  124.84 20.21 180 top
PC4533  SC1KP50V2KX-1DLGP  [C402H22]  128.52 17.42 90 bottom
PC4542  SC22U6D3V3MX-1-DL-GP  [C603H40]  113.79 25.8 0 bottom
PC4543  SCD1U25V2KX-1-DL-GP  [C402H22]  118.87 26.43 0 bottom
PC4601  SC2200P50V2KX-2DLGP  [C402H22]  39.37 70.76 0 bottom
PC4602  SCD1U25V2KX-1-DL-GP  [C402H22]  47.12 83.97 180 bottom
PC4603  SCD1U25V2KX-1-DL-GP  [C402H22]  37.97 80.03 270 bottom
PC4604  SC330P50V2KX-3-DL-GP  [C402H22]  49.78 83.84 180 bottom
PC4605  SCD047U25V2KX-4-GP  [C402H22]  40.01 78.12 180 bottom
PC4606  SCD22U25V3KX-DL-GP  [C603H36]  41.66 80.41 90 bottom
PC4607  SC1U10V2KX-1DLGP  [C402H22]  44.7 78.38 270 top
PC4608  SCD022U16V2KX-3DLGP  [C402H22]  37.97 78.5 90 bottom
PC4610  SC33P50V2JN-3DLGP  [C402H22]  49.78 81.04 270 top
PC4611  SC2200P50V2KX-2DLGP  [C402H22]  40.01 80.16 180 bottom
PC4612  SC2200P50V2KX-2DLGP  [C402H22]  49.53 82.95 0 top
PC4613  SCD01U25V2KX-3DLGP  [C402H22]  41.91 76.73 90 top
PC4614  SC470P50V2KX-3DLGP  [C402H22]  50.77 76.68 270 top
PC4615  SCD01U50V2KX-1DLGP  [C402H22]  51.18 72.59 270 top
PC4616  SC1KP50V2KX-1DLGP  [C402H22]  40.01 76.47 180 bottom
PC4617  SC1KP50V2KX-1DLGP  [C402H22]  38.35 74.95 0 bottom
PC4618  SC470P50V2KX-3DLGP  [C402H22]  51.31 74.11 270 top
PC4619  SC1KP50V2KX-1DLGP  [C402H22]  50.04 72.54 0 top
PC4620  SCD01U50V2KX-1DLGP  [C402H22]  37.85 72.15 180 bottom
PC4621  SC680P50V2KX-2DLGP  [C402H22]  38.99 72.79 270 bottom
PC4622  SCD01U25V2KX-3DLGP  [C402H22]  48.9 70.38 0 top
PC4623  SC2200P50V2KX-2DLGP  [C402H22]  48.51 84.47 180 top
PC4624  SC33P50V2JN-3DLGP  [C402H22]  39.75 72.03 90 bottom
PC4625  SCD022U16V2KX-3DLGP  [C402H22]  52.83 84.98 270 top
PC4626  SCD022U16V2KX-3DLGP  [C402H22]  51.44 84.35 180 top
PC4628  SCD022U16V2KX-3DLGP  [C402H22]  52.7 75.84 90 top
PC4629  SC330P50V2KX-3-DL-GP  [C402H22]  42.29 75.08 270 top
PC4630  SCD047U25V2KX-4-GP  [C402H22]  50.67 77.87 180 top
PC4631  SCD1U25V2KX-1-DL-GP  [C402H22]  39.75 70.12 90 top
PC4632  SC2200P50V2KX-2DLGP  [C402H22]  40.13 72.28 0 top
PC4633  SCD1U25V2KX-1-DL-GP  [C402H22]  51.94 79.14 270 top
PC4634  SCD047U25V2KX-4-GP  [C402H22]  42.29 68.6 90 top
PC4635  SCD01U25V2KX-3DLGP  [C402H22]  43.43 70.63 180 top
PC4637  SCD01U25V2KX-3DLGP  [C402H22]  42.16 70.76 270 bottom
PC4638  SC330P50V2KX-3-DL-GP  [C402H22]  46.61 70.25 180 bottom
PC4639  SC33P50V2JN-3DLGP  [C402H22]  45.09 70.63 90 top
PC4640  SC2200P50V2KX-2DLGP  [C402H22]  45.47 69.36 180 top
PC4641  SC330P50V2KX-3-DL-GP  [C402H22]  45.85 67.46 180 bottom
PC4642  SC1KP50V2KX-1DLGP  [C402H22]  42.16 69.23 270 bottom
PC4643  SC1KP50V2KX-1DLGP  [C402H22]  44.58 67.84 90 bottom
PC4644  SCD01U50V2KX-1DLGP  [C402H22]  43.31 67.46 180 bottom
PC4651  SC1KP50V2KX-1DLGP  [C402H22]  47.88 82.95 0 top
PC4652  SCD022U16V2KX-3DLGP  [C402H22]  42.67 70.63 180 top
PC4653  SCD047U25V2KX-4-GP  [C402H22]  52.7 77.36 90 top
PC4654  SCD01U25V2KX-3DLGP  [C402H22]  52.7 76.6 90 top
PC4702  SC10U25V3MX-GP  [C603H40]  55.24 67.96 0 bottom
PC4703  SC10U25V3MX-GP  [C603H40]  57.78 67.96 0 bottom
PC4704  SC10U25V3MX-GP  [C603H40]  56.52 67.96 0 bottom
PC4706  SC1KP50V2KX-1DLGP  [C402H22]  62.61 63.77 180 top
PC4707  SCD22U25V3KX-DL-GP  [C603H36]  54.23 62.27 270 bottom
PC4708  SC1U10V2KX-1DLGP  [C402H22]  54.23 59.58 180 bottom
PC4766  SC1U10V2KX-1DLGP  [C402H22]  59.56 59.58 90 top
PC4802  SC10U25V3MX-GP  [C603H40]  59.56 87.65 270 bottom
PC4803  SC10U25V3MX-GP  [C603H40]  59.56 85.87 270 bottom
PC4804  SC10U25V3MX-GP  [C603H40]  57.66 88.16 0 bottom
PC4805  SC10U25V3MX-GP  [C603H40]  56.39 87.39 0 bottom
PC4808  SCD22U25V3KX-DL-GP  [C603H36]  53.72 86.51 270 bottom
PC4809  SC1U10V2KX-1DLGP  [C402H22]  53.98 83.46 90 bottom
PC4810  SC1KP50V2KX-1DLGP  [C402H22]  62.61 84.35 180 top
PC4811  SCD22U25V3KX-DL-GP  [C603H36]  54.99 73.17 270 bottom
PC4812  SC1U10V2KX-1DLGP  [C402H22]  56.26 70.12 90 top
PC4813  SC1KP50V2KX-1DLGP  [C402H22]  63.5 75.2 180 top
PC4814  SC10U25V3MX-GP  [C603H40]  49.15 72.03 90 bottom
PC4815  SC10U25V3MX-GP  [C603H40]  59.44 76.73 270 bottom
PC4816  SC10U25V3MX-GP  [C603H40]  49.15 73.68 90 bottom
PC4817  SC10U25V3MX-GP  [C603H40]  60.07 78 270 bottom
PC4866  SC1U10V2KX-1DLGP  [C402H22]  59.82 69.23 90 top
PC4877  SC1U10V2KX-1DLGP  [C402H22]  51.74 84.73 90 bottom
PC5001  SC2D2U10V3KX-1DLGP-U  [C603H36]  148.84 103.14 0 bottom
PC5002  SC10U25V5KX-DL-GP  [C805H58]  146.43 107.08 0 bottom
PC5003  SC10U25V5KX-DL-GP  [C805H58]  147.07 104.16 180 bottom
PC5004  SCD1U25V2KX-1-DL-GP  [C402H22]  145.67 104.67 180 bottom
PC5005  SCD22U25V3KX-DL-GP  [C603H36]  150.88 105.81 180 bottom
PC5104  SC22U6D3V3MX-1-DL-GP  [C603H40]  142.37 23.77 90 bottom
PC5105  SC22U6D3V3MX-1-DL-GP  [C603H40]  142.37 26.31 90 bottom
PC5107  SC22U6D3V3MX-1-DL-GP  [C603H40]  142.37 27.58 90 bottom
PC5109  SC22U6D3V3MX-1-DL-GP  [C603H40]  142.37 25.04 90 bottom
PC5110  SC1U10V2KX-1DLGP  [C402H22]  151.51 21.48 90 bottom
PC5111  SC10U25V5KX-DL-GP  [C805H58]  155.02 28.72 0 bottom
PC5112  SC2D2U10V3KX-1DLGP-U  [C603H36]  149.48 21.74 90 bottom
PC5113  SC470P50V2KX-3DLGP  [C402H22]  154.56 21.1 0 bottom
PC5114  SCD1U25V2KX-1-DL-GP  [C402H22]  153.03 26.05 270 top
PC5115  SC10U25V5KX-DL-GP  [C805H58]  153.16 28.72 0 bottom
PC5116  SCD1U25V2KX-1-DL-GP  [C402H22]  156.34 28.85 0 bottom
PC5118  SCD1U25V2KX-1-DL-GP  [C402H22]  44.2 23.39 270 bottom
PC5119  SCD1U16V2KX-3DLGP  [C402H22]  49.63 25.01 270 bottom
PC5120  SCD1U16V2KX-3DLGP  [C402H22]  49.63 25.77 270 bottom
PC5121  SC1U10V2KX-1DLGP  [C402H22]  49.63 24.25 270 bottom
PC5122  SC10U6D3V3MX-DL-GP  [C603H36]  44.22 22.32 270 bottom
PC5123  SCD1U25V2KX-1-DL-GP  [C402H22]  49.63 26.54 270 bottom
PC5124  SC22U6D3V3MX-1-DL-GP  [C603H40]  41.99 25.34 180 bottom
PC5201  SC22U6D3V3MX-1-DL-GP  [C603H40]  169.04 64.28 90 bottom
PC5202  SC1U10V2KX-1DLGP  [C402H22]  178.18 60.09 270 bottom
PC5203  SC22U6D3V3MX-1-DL-GP  [C603H40]  169.04 65.68 90 bottom
PC5204  SCD1U25V2KX-1-DL-GP  [C402H22]  176.4 60.09 90 bottom
PC5205  SC22U6D3V3MX-1-DL-GP  [C603H40]  169.04 63.01 90 bottom
PC5206  SC22U6D3V3MX-1-DL-GP  [C603H40]  169.04 61.74 90 bottom
PC5208  SCD1U25V2KX-1-DL-GP  [C402H22]  173.18 68.24 180 top
PC5209  SC10U25V5KX-DL-GP  [C805H58]  170.69 56.15 0 bottom
PC5210  SC10U25V5KX-DL-GP  [C805H58]  172.97 55.64 0 bottom
PC5211  SC10U25V5KX-DL-GP  [C805H58]  172.21 52.72 180 bottom
PC5212  SC220P50V2KX-3DLGP  [C402H22]  181.61 54.88 0 bottom
PC5213  SCD01U25V2KX-3DLGP  [C402H22]  179.96 60.47 0 bottom
PC5214  SCD1U25V2KX-1-DL-GP  [C402H22]  173.86 52.47 180 bottom
PC5215  SCD1U16V2KX-3DLGP  [C402H22]  180.59 57.04 270 bottom
PC5216  SC10U25V5KX-DL-GP  [C805H58]  170.05 52.22 180 bottom
PC5301  SC1U10V2KX-1DLGP  [C402H22]  37.13 16.48 90 bottom
PC5302  SC10U6D3V3MX-DL-GP  [C603H36]  46.99 17.04 180 bottom
PC5303  SC10U6D3V3MX-DL-GP  [C603H36]  44.73 15.39 270 bottom
PC5304  SC22U6D3V3MX-1-DL-GP  [C603H40]  49.91 19.83 0 bottom
PC5305  SC68P50V2JN-1DLGP  [C402H22]  47.75 19.32 0 bottom
PC5306  SC4700P25V2KX-4-GP  [C402H22]  37.21 22.5 90 bottom
PC5310  SC1U10V2KX-1DLGP  [C402H22]  136.65 20.59 90 bottom
PC5311  SC68P50V2JN-1DLGP  [C402H22]  137.79 28.85 180 bottom
PC5312  SC22U6D3V3MX-1-DL-GP  [C603H40]  140.08 28.97 270 bottom
PC5313  SC10U6D3V3MX-DL-GP  [C603H36]  140.08 30.75 270 bottom
PC5314  SC10U6D3V3MX-DL-GP  [C603H36]  140.08 22.5 270 bottom
PC5327  SCD1U25V2KX-1-DL-GP  [C402H22]  129.92 15.51 180 bottom
PD4401  BAT54C-12-GP  [SOT-23-9H44]  38.99 30.5 0 bottom
PD4404  L1SS355T1G-GP  [SOD323AKH44]  40.89 41.93 0 bottom
PD4407  RB551V30-GP  [SOD323AKH38]  37.72 27.7 0 bottom
PD4408  BAT54C-12-GP  [SOT-23-9H44]  38.99 33.67 0 bottom
PG4401  GAP-CLOSE-PWR-3-GP  [GAP-CLOSE-PWR-3]  37.34 66.95 0 bottom
PG4402  GAP-CLOSE-PWR-3-GP  [GAP-CLOSE-PWR-3]  37.34 64.28 0 bottom
PG4405  GAP-CLOSE-PWR-3-GP  [GAP-CLOSE-PWR-3]  140.72 19.7 270 bottom
PG4406  GAP-CLOSE-PWR-3-GP  [GAP-CLOSE-PWR-3]  142.49 19.7 270 bottom
PG4408  GAP-CLOSE-PWR-3-GP  [GAP-CLOSE-PWR-3]  29.97 42.94 270 top
PG4501  GAP-CLOSE-PWR-3-GP  [GAP-CLOSE-PWR-3]  54.23 20.08 270 bottom
PG4502  GAP-CLOSE-PWR-3-GP  [GAP-CLOSE-PWR-3]  54.99 20.08 270 bottom
PG4503  GAP-CLOSE-PWR-3-GP  [GAP-CLOSE-PWR-3]  55.75 20.08 270 bottom
PG4504  GAP-CLOSE-PWR-3-GP  [GAP-CLOSE-PWR-3]  53.47 20.08 270 bottom
PG4505  GAP-CLOSE-PWR-3-GP  [GAP-CLOSE-PWR-3]  52.7 20.08 270 bottom
PG4506  GAP-CLOSE-PWR-3-GP  [GAP-CLOSE-PWR-3]  51.94 20.08 270 bottom
PG4507  GAP-CLOSE-PWR-3-GP  [GAP-CLOSE-PWR-3]  111.63 23.13 180 bottom
PG4508  GAP-CLOSE-PWR-3-GP  [GAP-CLOSE-PWR-3]  111.63 24.15 180 bottom
PG4509  GAP-CLOSE-PWR-3-GP  [GAP-CLOSE-PWR-3]  111.63 25.16 180 bottom
PG4510  GAP-CLOSE-PWR-3-GP  [GAP-CLOSE-PWR-3]  78.61 23.51 0 top
PG4511  GAP-CLOSE-PWR-3-GP  [GAP-CLOSE-PWR-3]  78.61 22.5 0 top
PG4512  GAP-CLOSE-PWR-3-GP  [GAP-CLOSE-PWR-3]  78.61 21.48 0 top
PG4513  GAP-CLOSE-PWR-3-GP  [GAP-CLOSE-PWR-3]  78.61 21.48 0 bottom
PG4515  GAP-CLOSE-PWR-3-GP  [GAP-CLOSE-PWR-3]  130.2 26.97 270 bottom
PG4516  GAP-CLOSE-PWR-3-GP  [GAP-CLOSE-PWR-3]  127.15 26.97 270 bottom
PG4517  GAP-CLOSE-PWR-3-GP  [GAP-CLOSE-PWR-3]  128.17 26.97 270 bottom
PG4518  GAP-CLOSE-PWR-3-GP  [GAP-CLOSE-PWR-3]  129.18 26.97 270 bottom
PG4519  GAP-CLOSE-PWR-3-GP  [GAP-CLOSE-PWR-3]  125.22 17.42 0 bottom
PG4520  GAP-CLOSE-PWR-3-GP  [GAP-CLOSE-PWR-3]  111.63 22.12 180 bottom
PG4521  GAP-CLOSE-PWR-3-GP  [GAP-CLOSE-PWR-3]  111.63 21.1 180 bottom
PG4522  GAP-CLOSE-PWR-3-GP  [GAP-CLOSE-PWR-3]  78.61 24.53 0 bottom
PG4523  GAP-CLOSE-PWR-3-GP  [GAP-CLOSE-PWR-3]  78.61 23.51 0 bottom
PG4524  GAP-CLOSE-PWR-3-GP  [GAP-CLOSE-PWR-3]  78.61 22.5 0 bottom
PG4525  GAP-CLOSE-PWR-3-GP  [GAP-CLOSE-PWR-3]  78.61 20.47 0 top
PG4526  GAP-CLOSE-PWR-3-GP  [GAP-CLOSE-PWR-3]  111.63 20.34 180 bottom
PG4527  GAP-CLOSE-PWR-3-GP  [GAP-CLOSE-PWR-3]  78.87 25.8 270 bottom
PG4528  GAP-CLOSE-PWR-3-GP  [GAP-CLOSE-PWR-3]  61.19 24.1 270 top
PG4529  GAP-CLOSE-PWR-3-GP  [GAP-CLOSE-PWR-3]  59.18 22.5 0 top
PG4530  GAP-CLOSE-PWR-3-GP  [GAP-CLOSE-PWR-3]  112.65 18.81 90 bottom
PG4531  GAP-CLOSE-PWR-3-GP  [GAP-CLOSE-PWR-3]  128.52 19.7 180 top
PG4707  GAP-CLOSE-PWR-3-GP  [GAP-CLOSE-PWR-3]  66.42 61.11 180 bottom
PG4708  GAP-CLOSE-PWR-3-GP  [GAP-CLOSE-PWR-3]  68.45 61.11 0 bottom
PG4808  GAP-CLOSE-PWR-3-GP  [GAP-CLOSE-PWR-3]  66.17 81.81 0 bottom
PG4809  GAP-CLOSE-PWR-3-GP  [GAP-CLOSE-PWR-3]  68.71 81.81 180 bottom
PG4813  GAP-CLOSE-PWR-3-GP  [GAP-CLOSE-PWR-3]  66.29 73.04 180 bottom
PG4815  GAP-CLOSE-PWR-3-GP  [GAP-CLOSE-PWR-3]  68.58 73.04 0 bottom
PG5001  GAP-CLOSE-PWR-3-GP  [GAP-CLOSE-PWR-3]  135.89 105.05 180 bottom
PG5002  GAP-CLOSE-PWR-3-GP  [GAP-CLOSE-PWR-3]  148.08 106.83 0 bottom
PG5003  GAP-CLOSE-PWR-3-GP  [GAP-CLOSE-PWR-3]  148.08 107.59 0 bottom
PG5011  GAP-CLOSE-PWR-3-GP  [GAP-CLOSE-PWR-3]  138.18 105.05 0 bottom
PG5105  GAP-CLOSE-PWR-3-GP  [GAP-CLOSE-PWR-3]  157.23 29.74 270 bottom
PG5110  GAP-CLOSE-PWR-3-GP  [GAP-CLOSE-PWR-3]  158.24 29.74 270 bottom
PG5112  GAP-CLOSE-PWR-3-GP  [GAP-CLOSE-PWR-3]  158.55 22.67 90 bottom
PG5113  GAP-CLOSE-PWR-3-GP  [GAP-CLOSE-PWR-3]  153.42 20.21 180 bottom
PG5114  GAP-CLOSE-PWR-3-GP  [GAP-CLOSE-PWR-3]  160.4 26.26 270 bottom
PG5201  GAP-CLOSE-PWR-3-GP  [GAP-CLOSE-PWR-3]  169.16 68.34 90 bottom
PG5202  GAP-CLOSE-PWR-3-GP  [GAP-CLOSE-PWR-3]  172.21 68.34 90 bottom
PG5203  GAP-CLOSE-PWR-3-GP  [GAP-CLOSE-PWR-3]  171.32 68.6 90 top
PG5204  GAP-CLOSE-PWR-3-GP  [GAP-CLOSE-PWR-3]  170.56 68.6 90 top
PG5205  GAP-CLOSE-PWR-3-GP  [GAP-CLOSE-PWR-3]  169.8 68.6 90 top
PG5206  GAP-CLOSE-PWR-3-GP  [GAP-CLOSE-PWR-3]  169.93 68.34 90 bottom
PG5207  GAP-CLOSE-PWR-3-GP  [GAP-CLOSE-PWR-3]  170.69 68.34 90 bottom
PG5208  GAP-CLOSE-PWR-3-GP  [GAP-CLOSE-PWR-3]  171.45 68.34 90 bottom
PG5209  GAP-CLOSE-PWR-3-GP  [GAP-CLOSE-PWR-3]  169.04 68.6 90 top
PG5210  GAP-CLOSE-PWR-3-GP  [GAP-CLOSE-PWR-3]  168.35 54.88 0 bottom
PG5211  GAP-CLOSE-PWR-3-GP  [GAP-CLOSE-PWR-3]  172.09 68.6 90 top
PG5212  GAP-CLOSE-PWR-3-GP  [GAP-CLOSE-PWR-3]  168.35 53.36 0 bottom
PG5214  GAP-CLOSE-PWR-3-GP  [GAP-CLOSE-PWR-3]  168.35 54.12 0 bottom
PG5223  GAP-CLOSE-PWR-6-GP  [GAP-CLOSE-PWR]  174.37 67.84 0 top
PL4401  COIL-2D2UH-72-GP  [L109100-2430-UH79]  43.81 58.44 270 bottom
PL4501  COIL-1UH-57-GP  [L7066-1830-UH95]  120.02 21.61 90 bottom
PL4502  COIL-1D5UH-29-GP  [L7066-1830-UH95]  70.38 21.13 90 bottom
PL4701  COIL-D15UH-8-GP  [L7366-1930H95]  67.44 61.11 270 bottom
PL4702  HCB2012KF-800T50-GP-U  [L20125H42]  55.63 64.15 270 bottom
PL4703  HCB2012KF-800T50-GP-U  [L20125H42]  55.63 65.8 270 bottom
PL4801  COIL-D15UH-8-GP  [L7366-1930H95]  67.44 81.81 270 bottom
PL4802  COIL-D15UH-8-GP  [L7366-1930H95]  67.44 73.04 270 bottom
PL4803  HCB2012KF-800T50-GP-U  [L20125H42]  51.18 71.65 0 bottom
PL4804  HCB2012KF-800T50-GP-U  [L20125H42]  52.83 71.65 0 bottom
PL5001  COIL-D47UH-20-GP  [L7066-1830-UH95]  137.03 105.05 90 bottom
PL5101  COIL-1UH-57-GP  [L7066-1830-UH95]  147.83 25.93 90 bottom
PL5201  COIL-1UH-57-GP  [L7066-1830-UH95]  174.5 64.03 90 bottom
PQ4405  2N7002KDW-1-GP  [SOT-363H44]  30.73 41.8 0 bottom
PQ4408  MMBT3906-3-GP  [SOT23CBE2D4H44]  40.39 37.74 0 bottom
PQ4415  2N7002KDW-1-GP  [SOT-363H44]  34.26 21.68 270 bottom
PQ4416  2N7002KDW-1-GP  [SOT-363H44]  32.38 36.47 0 bottom
PQ4417  2N7002K-2-GP  [SOT23DGS2D4H44]  34.92 26.82 0 bottom
PQ4418  2N7002KDW-1-GP  [SOT-363H44]  32.64 32.66 0 bottom
PR4401  D02R6F-GP  [R1206H24]  36.2 65.55 180 bottom
PR4402  2D2R3-1-U-GP  [R603H22]  36.07 51.2 180 top
PR4403  2D2R5J-1-GP  [R805H24]  30.48 47.64 90 bottom
PR4404  402KR2F-GP  [R402H16]  29.97 46.75 90 top
PR4405  4D7R2F-GP  [R402H16]  40.39 48.41 270 bottom
PR4406  100KR2F-L1-GP  [R402H16]  29.97 47.52 270 top
PR4407  D01R3721F-GP-U  [R3720H40]  141.6 16.78 270 bottom
PR4408  2D2R3-1-U-GP  [R603H22]  40.01 47.01 180 top
PR4409  100KR2F-L1-GP  [R402H16]  30.1 39.9 270 top
PR4410  105KR2F-1-GP  [R402H16]  31.37 41.29 180 top
PR4411  499R2F-2-GP  [R402H16]  32.13 41.29 0 top
PR4412  0R0402-PAD-1-GP  [0R0402-PAD]  33.66 41.29 0 top
PR4413  6K04R2F-GP  [R402H16]  34.42 41.29 0 top
PR4414  -  [0R0805-PAD]  43.69 64.79 270 top
PR4416  2D2R5J-1-GP  [R805H24]  38.48 58.44 0 top
PR4417  100KR2F-L1-GP  [R402H16]  29.97 45.99 90 top
PR4420  -  [0R0805-PAD]  45.97 55.14 270 top
PR4422  1R2F-GP  [R402H16]  33.91 53.61 180 bottom
PR4423  1R2F-GP  [R402H16]  34.67 53.61 180 bottom
PR4424  1R2F-GP  [R402H16]  37.47 38.63 180 bottom
PR4425  1R2F-GP  [R402H16]  36.7 38.63 180 bottom
PR4426  196KR2F-GP  [R402H16]  29.84 33.29 270 bottom
PR4427  100KR2F-L1-GP  [R402H16]  30.99 46.25 90 bottom
PR4429  100KR2F-L1-GP  [R402H16]  30.99 45.48 90 bottom
PR4435  100KR2F-L1-GP  [R402H16]  29.97 44.47 90 top
PR4436  1MR2J-1-GP  [R402H16]  40.51 35.71 270 bottom
PR4450  10KR2F-2-DL-GP  [R402H16]  29.84 37.61 180 bottom
PR4462  0R0402-PAD-1-GP  [0R0402-PAD]  34.16 41.42 90 bottom
PR4463  0R2J-2-GP  [R402H16]  30.99 44.72 90 bottom
PR4472  100KR2F-L1-GP  [R402H16]  30.23 36.34 270 bottom
PR4473  100KR2J-1-GP  [R402H16]  38.86 35.71 270 bottom
PR4474  100KR2F-L1-GP  [R402H16]  30.61 37.61 180 bottom
PR4475  680KR2F-GP  [R402H16]  34.16 40.66 90 bottom
PR4476  0R0402-PAD-1-GP  [0R0402-PAD]  32.89 41.17 0 bottom
PR4477  0R0402-PAD-1-GP  [0R0402-PAD]  40.39 44.47 0 bottom
PR4478  100R2F-L1-GP-U  [R402H14]  33.66 43.45 90 bottom
PR4479  100KR2J-1-GP  [R402H16]  31.5 27.96 90 bottom
PR4483  0R0402-PAD-1-GP  [0R0402-PAD]  29.79 31.77 270 bottom
PR4485  0R0402-PAD-1-GP  [0R0402-PAD]  36.07 33.17 180 bottom
PR4486  10KR2F-2-DL-GP  [R402H16]  31.5 28.72 270 bottom
PR4487  100KR2F-L1-GP  [R402H16]  33.15 29.74 90 bottom
PR4488  0R2J-2-GP  [R402H16]  29.84 32.53 90 bottom
PR4495  0R2J-2-GP  [R402H16]  35.18 35.71 90 bottom
PR4501  0R0603-PAD-1-GP-U  [0R0603-PAD-U]  123.32 25.8 90 bottom
PR4502  0R0603-PAD-1-GP-U  [0R0603-PAD-U]  65.53 16.78 270 bottom
PR4503  0R2J-L-GP  [R402H15]  128.4 18.31 180 top
PR4504  0R0402-PAD-1-GP  [0R0402-PAD]  58.55 25.55 270 bottom
PR4505  100KR2J-1-GP  [R402H16]  129.29 19.45 90 bottom
PR4506  1KR2F-3-GP  [R402H16]  126.87 17.42 270 bottom
PR4507  1KR2F-3-GP  [R402H16]  62.87 25.93 180 bottom
PR4508  200KR2F-L-GP  [R402H16]  130.18 17.93 270 bottom
PR4509  1KR2F-3-GP  [R402H16]  130.18 17.16 90 bottom
PR4510  100KR2J-1-GP  [R402H16]  60.33 23.51 180 top
PR4511  1KR2F-3-GP  [R402H16]  59.05 24.66 270 bottom
PR4512  200KR2F-L-GP  [R402H16]  59.05 23.89 90 bottom
PR4513  1MR2J-1-GP  [R402H16]  59.82 25.93 0 bottom
PR4514  1MR2J-1-GP  [R402H16]  125.6 20.21 180 top
PR4515  0R0402-PAD-1-GP  [0R0402-PAD]  127.64 18.31 0 top
PR4516  0R0402-PAD-1-GP  [0R0402-PAD]  126.36 18.31 180 top
PR4530  0R2J-L-GP  [R402H15]  58.55 26.31 270 bottom
PR4551  348KR2F-GP  [R402H16]  61.34 25.93 0 bottom
PR4601  0R0402-PAD-1-GP  [0R0402-PAD]  38.76 76.09 90 bottom
PR4602  0R0402-PAD-1-GP  [0R0402-PAD]  38.76 76.85 90 bottom
PR4603  1KR2F-3-GP  [R402H16]  46.35 83.97 180 bottom
PR4604  100R2F-L1-GP-U  [R402H14]  44.07 83.97 180 bottom
PR4605  75R2F-2-GP  [R402H16]  44.83 83.97 180 bottom
PR4606  45D3R2F-L-GP  [R402H16]  45.59 83.97 180 bottom
PR4607  100R2F-L1-GP-U  [R402H14]  45.85 81.68 180 bottom
PR4608  100KR2F-L1-GP  [R402H16]  50.55 83.84 180 bottom
PR4609  10KR2F-2-DL-GP  [R402H16]  48.13 83.84 180 bottom
PR4610  1R2J-GP  [R402H16]  45.21 80.54 270 top
PR4611  NTC-10K-29-GP-U  [NTC-402H22-U]  132.33 102.13 0 bottom
PR4612  0R0402-PAD-1-GP  [0R0402-PAD]  43.31 83.97 180 bottom
PR4613  0R2J-L-GP  [R402H15]  37.97 79.27 90 bottom
PR4614  0R2J-L-GP  [R402H15]  49.02 83.84 0 bottom
PR4615  1KR2F-3-GP  [R402H16]  39.88 81.43 270 bottom
PR4616  12K4R2F-GP  [R402H16]  50.29 81.68 180 bottom
PR4617  NTC-470K-17-GP  [NTC-402H22-U]  57.78 79.01 270 bottom
PR4618  11KR2F-L-GP  [R402H16]  39.24 78.12 0 bottom
PR4620  511R2F-2-GP  [R402H16]  39.24 80.16 180 bottom
PR4621  27K4R2F-GP  [R402H16]  51.05 81.68 0 bottom
PR4622  10R2F-L-GP  [R402H14]  43.56 81.68 180 bottom
PR4623  0R0402-PAD-1-GP  [0R0402-PAD]  44.32 81.68 180 bottom
PR4624  49D9R2F-GP  [R402H16]  45.09 81.68 180 bottom
PR4625  2K61R2F-1-GP  [R402H16]  37.97 77.74 90 bottom
PR4626  3K3R2F-2-GP  [R402H16]  49.91 81.81 270 top
PR4627  100R2F-L1-GP-U  [R402H14]  41.91 75.96 270 top
PR4628  9K31R2F-GP  [R402H16]  42.8 78 0 top
PR4629  100KR2F-L1-GP  [R402H16]  43.56 78 0 top
PR4630  2KR2F-L1-GP  [R402H16]  50.16 75.84 270 top
PR4631  100R2F-L1-GP-U  [R402H14]  51.31 73.35 90 top
PR4632  301R2F-GP  [R402H16]  39.62 74.57 270 bottom
PR4633  2K55R2F-GP  [R402H16]  50.04 74.57 180 top
PR4636  499R2F-2-GP  [R402H16]  51.31 74.87 270 top
PR4637  1K78R2F-GP  [R402H16]  39.62 75.33 90 bottom
PR4638  2KR2F-L1-GP  [R402H16]  40.13 73.3 0 bottom
PR4639  100R2F-L1-GP-U  [R402H14]  48.13 70.38 0 top
PR4640  2K49R2F-2-L-GP  [R402H16]  40.13 70.76 180 bottom
PR4641  2K61R2F-1-GP  [R402H16]  52.83 85.74 270 top
PR4642  523R2F-GP  [R402H16]  50.42 86.38 90 top
PR4643  11KR2F-L-GP  [R402H16]  51.44 77.87 180 top
PR4644  40K2R2F-GP  [R402H16]  42.29 74.31 90 top
PR4645  1KR2F-3-GP  [R402H16]  49.78 84.09 90 top
PR4646  NTC-10K-29-GP-U  [NTC-402H22-U]  66.17 85.74 270 bottom
PR4647  0R0402-PAD-1-GP  [0R0402-PAD]  52.7 78.12 270 top
PR4648  365R2F-GP  [R402H16]  39.75 71.01 270 top
PR4649  0R0402-PAD-1-GP  [0R0402-PAD]  42.29 69.36 90 top
PR4650  NTC-10K-29-GP-U  [NTC-402H22-U]  65.66 57.17 270 bottom
PR4651  1KR2F-3-GP  [R402H16]  39.37 72.28 0 top
PR4652  11KR2F-L-GP  [R402H16]  42.29 67.84 270 top
PR4653  2K61R2F-1-GP  [R402H16]  42.29 67.07 270 top
PR4654  NTC-470K-17-GP  [NTC-402H22-U]  56.9 58.95 180 bottom
PR4655  23K2R2F-GP  [R402H16]  46.61 67.46 0 bottom
PR4656  2K87R2F-1-GP  [R402H16]  44.7 69.36 0 top
PR4657  2KR2F-L1-GP  [R402H16]  44.96 70.25 180 bottom
PR4658  499R2F-2-GP  [R402H16]  44.2 70.25 180 bottom
PR4659  100R2F-L1-GP-U  [R402H14]  42.16 70 90 bottom
PR4660  1K91R2F-1-GP  [R402H16]  43.43 70.25 180 bottom
PR4661  84K5R2F-GP  [R402H16]  47.37 70.25 180 bottom
PR4662  10K2R2F-GP  [R402H16]  45.75 70.25 180 bottom
PR4663  100R2F-L1-GP-U  [R402H14]  44.2 65.68 90 bottom
PR4665  0R0402-PAD-1-GP  [0R0402-PAD]  48.77 72.54 90 top
PR4666  0R0402-PAD-1-GP  [0R0402-PAD]  48.77 71.77 90 top
PR4667  0R0402-PAD-1-GP  [0R0402-PAD]  42.55 67.46 180 bottom
PR4668  0R0402-PAD-1-GP  [0R0402-PAD]  41.78 67.46 180 bottom
PR4669  0R2J-L-GP  [R402H15]  46.35 74.57 90 top
PR4701  0R0402-PAD-1-GP  [0R0402-PAD]  39.75 69.36 270 top
PR4702  0R0402-PAD-1-GP  [0R0402-PAD]  59.69 56.66 90 bottom
PR4703  2D2R6J-3-GP  [R1206H28]  64.14 61.23 270 top
PR4704  2D2R2F-GP  [R402H16]  54.99 59.2 180 bottom
PR4705  2D2R3-1-U-GP  [R603H22]  54.23 61 270 bottom
PR4706  0R0402-PAD-1-GP  [0R0402-PAD]  60.58 55.9 90 bottom
PR4708  3K65R2F-1-GP  [R402H16]  41.91 70.63 180 top
PR4712  5K11R2F-L1-GP  [R402H16]  59.69 57.42 270 bottom
PR4802  0R0402-PAD-1-GP  [0R0402-PAD]  53.95 81.43 0 bottom
PR4803  2D2R2F-GP  [R402H16]  53.98 84.22 270 bottom
PR4804  2D2R3-1-U-GP  [R603H22]  53.72 85.24 270 bottom
PR4805  2D2R6J-3-GP  [R1206H28]  64.19 82.54 270 top
PR4806  0R0402-PAD-1-GP  [0R0402-PAD]  53.98 82.7 270 bottom
PR4808  3K65R2F-1-GP  [R402H16]  53.09 79.39 180 top
PR4809  10R2F-L-GP  [R402H14]  51.44 80.92 0 top
PR4810  2D2R3-1-U-GP  [R603H22]  54.99 71.9 270 bottom
PR4811  0R0402-PAD-1-GP  [0R0402-PAD]  58.17 69.49 180 top
PR4812  0R0402-PAD-1-GP  [0R0402-PAD]  56.39 70.12 90 bottom
PR4813  2D2R2F-GP  [R402H16]  56.26 69.36 270 top
PR4814  2D2R6J-3-GP  [R1206H28]  64.14 72.79 270 top
PR4815  10R2F-L-GP  [R402H14]  50.29 79.14 90 top
PR4816  3K65R2F-1-GP  [R402H16]  49.91 77.87 180 top
PR4817  5K11R2F-L1-GP  [R402H16]  54.71 81.43 180 bottom
